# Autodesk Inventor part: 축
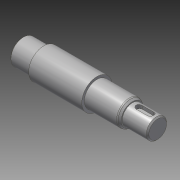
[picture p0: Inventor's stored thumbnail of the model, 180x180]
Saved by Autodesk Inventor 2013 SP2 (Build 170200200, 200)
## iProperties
Created: 2016-06
Part Number: 축
Material: 강철, 연강
Document SubType Name: Modeling
Designer: mduedu
Density: 7.86 g/cm^3
Author: mduedu
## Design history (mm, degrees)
sketch "스케치1"
  geometry: L1 (-53.5, 0)-(53.5, 0); L2 (-53.5, 0)-(-53.5, 10); L3 (-53.5, 10)-(-36.5, 10); L4 (-36.5, 10)-(-36.5, 12); L5 (-36.5, 12)-(5.5, 12); L6 (5.5, 12)-(5.5, 10); L7 (5.5, 10)-(33.5, 10); L8 (33.5, 10)-(33.5, 8); L9 (33.5, 8)-(53.5, 8); L10 (53.5, 8)-(53.5, 0); 2 further points
  constraints: 20 end point, 5 parallel, 2 perpendicular, 1 coincident, 1 collinear, 1 horizontal, 1 midpoint, 1 vertical
  dimensions: "d0" = 107 distance of L1.start L1.end; "d2" = 16 diameter of L9 L1; "d3" = 20 diameter of L7 L1; "d4" = 24 diameter of L5 L1; "d5" = 20 diameter of L3 L1; "d6" = 17 distance of L2.end L3.end; "d7" = 20 distance of L8.end L9.end; "d8" = 48 distance from line of L5.end L10
revolve "회전1" sketch "스케치1" stored, may be unused: angle "d9" = 90 deg
chamfer "모따기1" distance "d10" = 2; stored, may be unused: second distance "d11" = 2, angle "d12" = 30 deg
fillet "모깎기1" dims "d13" = 2
node "작업 평면1"
sketch "스케치2"
  geometry: L1 (-4.5, 2.5)-(4.5, 2.5); L2 (4.5, -2.5)-(-4.5, -2.5); L3 (-4.5, 0)-(4.5, 0); L4 (-10, 8.845)-(-10, -8.845) reference; A1 r 2.5 centre (-4.5, 0) between (-4.5, 2.5) and (-4.5, -2.5); A2 r 2.5 centre (4.5, 0) between (4.5, -2.5) and (4.5, 2.5); 1 further point
  constraints: 6 end point, 4 point on circle, 3 tangent, 2 centre point, 2 parallel, 1 horizontal, 1 horizontal alignment
  dimensions: "d14" = 3 distance edge to line of A1 L4; "d15" = 5 distance between parallel lines of L2 L1; "d16" = 14 dimension on A2 A1
extrude "돌출1" cut sketch "스케치2" distance "d17" = 3; taper "d18" = 0 deg
chamfer "모따기2" distance "d19" = 1; stored, may be unused: second distance "d20" = 2, angle "d21" = 30 deg
sketch "스케치3"
  geometry: L1 (-33.5, -8)-(-52.5, -8) reference; L2 (-53.5, -7)-(-53.5, 7) reference; L3 (-36, -8)-(-37.5, -6.5); L4 (-37.5, -6.5)-(-37.5, -8); L5 (-36, -8)-(-37.5, -8); 1 further point
  constraints: 6 end point, 2 point on line, 1 collinear, 1 vertical
  dimensions: "d22" = 45 deg angle of L4 L3; "d23" = 16 distance between parallel lines of L2 L4; "d24" = 3 diameter of L3.start L4
revolve "회전2" stored, may be unused: angle "d25" = 90 deg
node "작업점1"
sketch "스케치4"
  geometry: 1 further point
hole "구멍1" sketch "스케치4" at (0, 0) diameter "d26" = 3.242; stored, may be unused: countersink angle "d30" = 90 deg, drill point angle "d32" = 120 deg; dims "d27" = 8, "d28" = 4, "d29" = 2, "d31" = 11
chamfer "모따기3" distance "d33" = 2; stored, may be unused: second distance "d34" = 2, angle "d35" = 30 deg
node "솔리드1"
